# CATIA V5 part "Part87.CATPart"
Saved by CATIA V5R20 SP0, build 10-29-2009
Part number: 9FA 053012
Revision: ANY
Definition: UNKNOWN
Nomenclature: 9FA 053012
Source: Unknown
Bounding box of the stored display mesh (mm): x -2.5 to 2.5, y -6.775 to 5.225, z -2.5 to 2.5
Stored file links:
  C:\Users\Utente\Desktop\IO LAVORO\3D X SITO CF\CUMSA\3D files FA\FA 053012-21\Part87.CATPart

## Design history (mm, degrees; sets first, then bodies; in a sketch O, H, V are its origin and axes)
Set1 "FacciaKO#NONE#6979"
  DatumSurface1 "Sup6979_1"
  DatumCurve1 "Crv6979_1"
  Line1 "PCrv6979_1": stored without definition
  Line2 "PCrv6979_2": stored without definition
Set2
  DatumSurface2 "NONE"
Body1 (main body)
